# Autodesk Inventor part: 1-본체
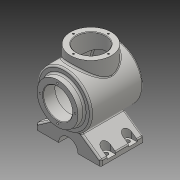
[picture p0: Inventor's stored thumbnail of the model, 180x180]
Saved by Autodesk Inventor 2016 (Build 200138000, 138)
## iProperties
Created: 2017-04
Part Number: 1-본체
Material: 일반
Document SubType Name: Modeling
Designer: H
Density: 1 g/cm^3
Appearance: 기본값
Author: H
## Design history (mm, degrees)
sketch "스케치1"
  geometry: L1 (-50, 0)-(46.336, 0); L2 (46.336, 0)-(46.336, 50); L3 (46.336, 50)-(-50, 50); L4 (-50, 50)-(-50, 0); L5 (-50, 0)-(-62, 0); L6 (-62, 0)-(-62, 38); L7 (-62, 38)-(-50, 38); L8 (-50, 38)-(-50, 0); L9 (46.336, 0)-(58, 0); A1 r 113 centre (-55, 0) between (58, 0) and (46.336, 50); 1 further point
  constraints: 18 end point, 4 parallel, 3 horizontal, 2 perpendicular, 2 point on circle, 2 point on line, 1 centre point
  dimensions: "d0" = 50 distance from line of point (0, 0) L4; "d1" = 108 distance of L9.end L1.start; "d2" = 12 distance between parallel lines of L4 L6; "d3" = 76 diameter of L7 L5; "d4" = 100 diameter of L3 L1; "d5" = 113 radius of A1
revolve "회전1" sketch "스케치1" stored, may be unused: angle "d6" = 90 deg
sketch "스케치2"
  geometry: C1 r 38 at (0, 0); 1 further point
  constraints: 1 centre point, 1 coincident
  dimensions: "d7" = 76 diameter of C1
extrude "돌출1" join sketch "스케치2" distance "d8" = 65; taper "d9" = 0 deg
sketch "스케치3"
  geometry: L1 (-50, 50)-(46.336, 50) reference; L2 (-50, -50)-(46.336, -50) reference; L3 (-50, -50)-(-50, 50) reference; L4 (39.916, 40)-(-40, 40); L5 (-40, 40)-(-40, 0); L6 (-40, 0)-(48, 0); A1 r 113 centre (-55, 0) between (46.336, -50) and (46.336, 50) reference; A2 r 103 centre (-55, 0) between (48, 0) and (39.916, 40); 1 further point
  constraints: 6 end point, 2 point on circle, 1 centre point, 1 horizontal, 1 point on line, 1 other
  dimensions: "d10" = 10 radial gap between concentric circles of A1 A2; "d11" = 10 distance between parallel lines of L5 L3
revolve "회전2" sketch "스케치3" stored, may be unused: angle "d12" = 90 deg
hole "구멍1" diameter "d15" = 54; stored, may be unused: countersink angle "d19" = 90 deg, drill point angle "d21" = 118 deg; dims "d13" = 10, "d14" = 10, "d16" = 6, "d17" = 4, "d18" = 2, "d20" = 22
hole "구멍2" diameter "d24" = 54; stored, may be unused: countersink angle "d28" = 90 deg, drill point angle "d30" = 118 deg; dims "d22" = 10, "d23" = 10, "d25" = 6, "d26" = 4, "d27" = 2, "d29" = 22
node "작업 평면2"
sketch "스케치5"
  geometry: L1 (60, -72)-(-60, -72); L2 (-60, -72)-(-60, -82); L3 (-60, -82)-(60, -82); L4 (60, -82)-(60, -72); 2 further points
  constraints: 8 end point, 2 parallel, 1 horizontal, 1 midpoint, 1 perpendicular, 1 vertical alignment
  dimensions: "d38" = 10 distance of L1.end L2.end; "d39" = 82 distance from line of L3 point (0, 0); "d40" = 120 distance of L2.end L3.end
extrude "돌출3" join sketch "스케치5" distance "d41" = 80; taper "d42" = 0 deg
sketch "스케치6"
  geometry: L1 (-60, -72)-(60, -72) reference; L2 (-60, -72)-(-21.584, -45.101); L3 (-60, -82)-(-60, -72) reference; L4 (60, -72)-(21.584, -45.101); L5 (60, -72)-(60, -82) reference; A1 r 50 centre (0, 0) between (-21.584, -45.101) and (21.584, -45.101) reference; 1 further point
  constraints: 4 end point, 2 point on circle
  dimensions: "d43" = 55 deg angle of L3 L2; "d44" = 55 deg angle of L5 L4 (= d43)
extrude "돌출4" join sketch "스케치6" distance "d45" = 80; taper "d46" = 0 deg
sketch "스케치7"
  geometry: L1 (60, -82)-(-60, -82) reference; C1 r 18 at (0, -82); 2 further points
  constraints: 1 centre point, 1 coincident, 1 midpoint
  dimensions: "d48" = 18 radius of C1
extrude "돌출5" cut sketch "스케치7" stored distance "d49" = 80; taper "d50" = 0 deg
node "작업 평면4"
sketch "스케치9"
  geometry: L1 (0, 0)-(0, 80) reference; L2 (10, 60)-(0, 60); L3 (10, 68)-(0, 68); L4 (0, 52)-(10, 52); L5 (10, 20)-(0, 20); L6 (10, 28)-(0, 28); L7 (0, 12)-(10, 12); L8 (120, 0)-(120, 80) reference; L9 (110, 60)-(120, 60); L10 (110, 52)-(120, 52); L11 (120, 68)-(110, 68); L12 (110, 20)-(120, 20); L13 (110, 12)-(120, 12); L14 (120, 28)-(110, 28); L15 (110, 20)-(10, 20); L16 (10, 20)-(10, 60); L17 (10, 60)-(110, 60); L18 (110, 60)-(110, 20); L19 (78, 0)-(120, 0) reference; A1 r 8 centre (10, 60) between (10, 52) and (10, 68); A2 r 8 centre (0, 60) between (0, 68) and (0, 52); A3 r 8 centre (10, 20) between (10, 12) and (10, 28); A4 r 8 centre (0, 20) between (0, 28) and (0, 12); A5 r 8 centre (110, 60) between (110, 68) and (110, 52); A6 r 8 centre (120, 60) between (120, 52) and (120, 68); A7 r 8 centre (110, 20) between (110, 28) and (110, 12); A8 r 8 centre (120, 20) between (120, 12) and (120, 28); 6 further points
  constraints: 40 end point, 16 point on circle, 16 tangent, 8 centre point, 6 parallel, 5 midpoint, 5 perpendicular, 4 point on line, 1 horizontal, 1 vertical alignment
  dimensions: "d55" = 8 radius of A1; "d56" = 8 radius of A5 (= d55); "d57" = 8 radius of A7 (= d55); "d58" = 8 radius of A3 (= d55); "d109" = 40 distance of L5.start L2.start; "d110" = 100 distance of L12.start L5.start; "d111" = 20 distance between parallel lines of L19 L15
extrude "돌출6" cut sketch "스케치9" distance "d59" = 30; taper "d60" = 0 deg
fillet "모깎기1" dims "d61" = 3
fillet "모깎기2" dims "d62" = 3
fillet "모깎기3" dims "d63" = 3
fillet "모깎기4" dims "d64" = 3
fillet "모깎기5" dims "d65" = 3
chamfer "모따기1" distance "d66" = 1; stored, may be unused: second distance "d67" = 2, angle "d68" = 45 deg
sketch "스케치10" dims "d69" = 65
  geometry: L1 (0, 0)-(0, 32.5); 1 further point
  constraints: 2 end point, 1 coincident, 1 vertical, 1 vertical alignment, 2 other
hole "구멍3" sketch "스케치10" at (0, 32.5) diameter "d70" = 3.242; stored, may be unused: countersink angle "d74" = 90 deg, drill point angle "d76" = 118 deg; dims "d71" = 8, "d72" = 4, "d73" = 2, "d75" = 10
sketch "스케치11" dims "d80" = 65
  geometry: L1 (0, 0)-(-32.5, 0); 1 further point
  constraints: 2 end point, 1 coincident, 1 horizontal, 1 horizontal alignment, 2 other
hole "구멍4" sketch "스케치11" at (-32.5, 0) diameter "d81" = 3.242; stored, may be unused: countersink angle "d85" = 90 deg, drill point angle "d87" = 118 deg; dims "d82" = 8, "d83" = 4, "d84" = 2, "d86" = 10
node "작업 평면5"
sketch "스케치12"
  geometry: 2 further points
  constraints: 1 coincident, 1 other
feature "엠보싱1" sketch "스케치12" dims "d0" = 50, "d1" = 108, "d2" = 12, "d3" = 76, "d4" = 100, "d5" = 113, "d91" = 0.5, "d92" = 0
hole "구멍5" diameter "d95" = 8; stored, may be unused: countersink angle "d99" = 90 deg, drill point angle "d101" = 118 deg; dims "d93" = 10, "d94" = 10, "d96" = 8, "d97" = 4, "d98" = 2, "d100" = 10
fillet "모깎기6" dims "d108" = 3
node "솔리드1"
pattern_circular "원형 패턴1" dims angle "d78" = 360 deg
pattern_circular "원형 패턴2" dims angle "d89" = 360 deg
pattern_linear "직사각형 패턴1" dims "d104" = 40
other parameters: "d37" = -42, "d52" = -6
